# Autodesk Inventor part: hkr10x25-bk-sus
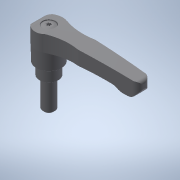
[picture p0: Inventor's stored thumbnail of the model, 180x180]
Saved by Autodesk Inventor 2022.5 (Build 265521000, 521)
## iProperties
Created: 2017-09
Part Number: hkr10x25-bk-sus
Material: 一般
Document SubType Name: Modeling
Designer: imaocorp
Density: 1 g/cm^3
Appearance: 既定
Author: imaocorp
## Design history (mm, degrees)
node "hkr10x25-bk-sus.x_t1"
node "hkr10x25-bk-sus"
node "Base1"
